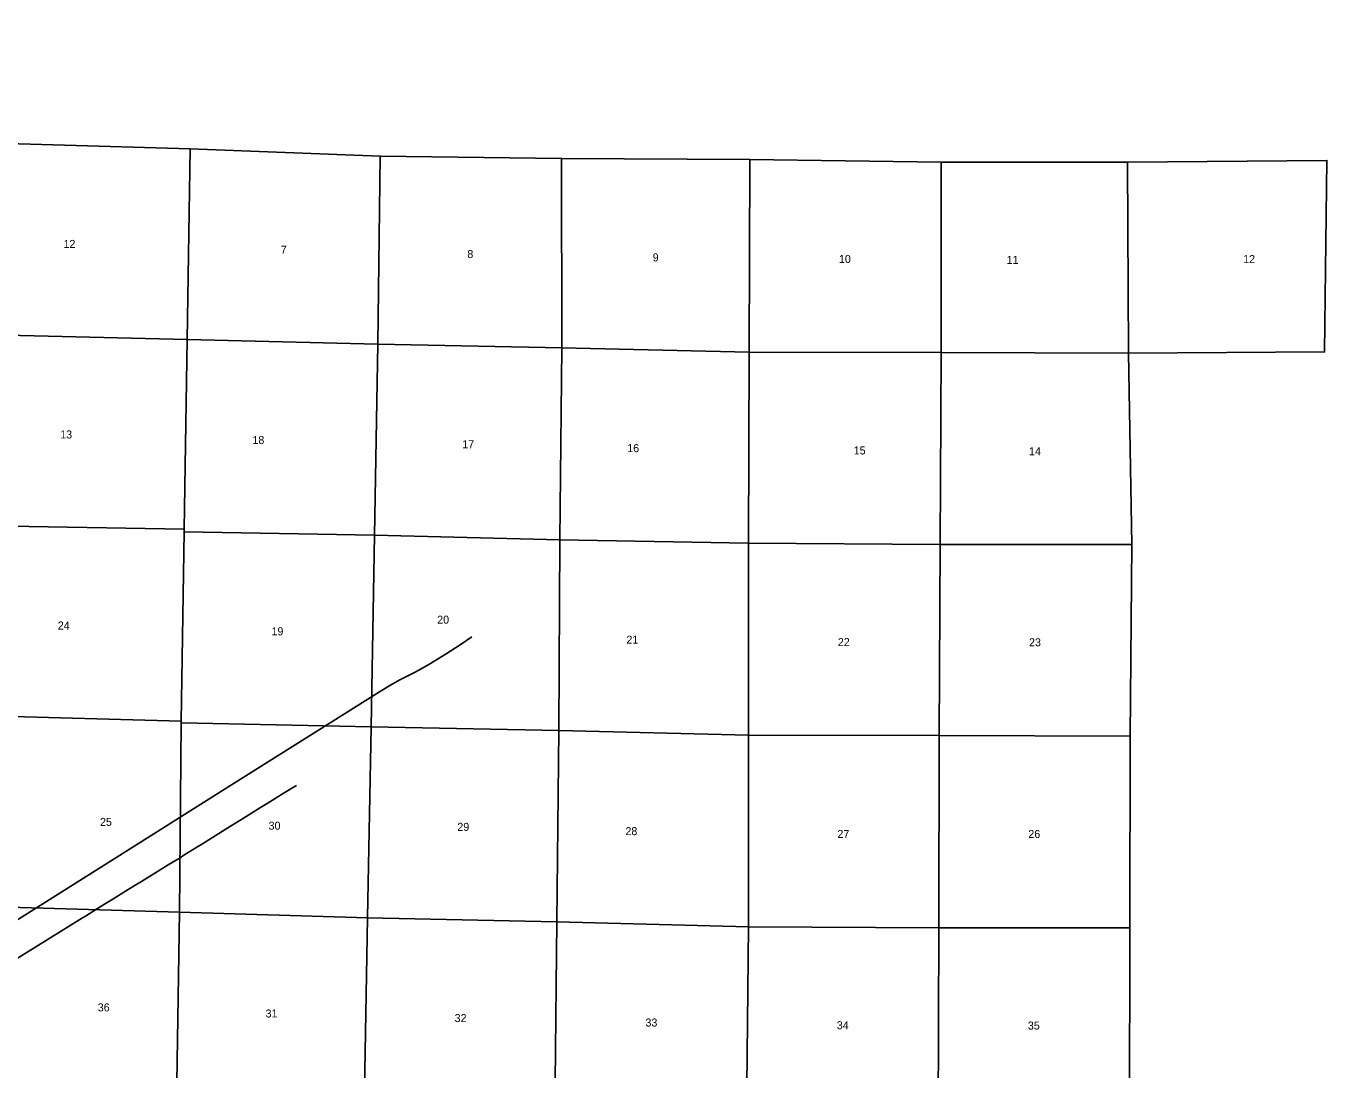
# Model space of a CAD drawing. Extents: x 1587405 to 1714697, y 1028970 to 1155083.
# Drawn here: x 1678758 to 1714697, y 1124403 to 1153249 of the extents above; entities that cross this region are included whole.
import ezdxf

# ---------------------------------------------------------------- set-up
doc = ezdxf.new("R2010")
doc.units = 0
for name, color, linetype in [('GM_X_Rail_Line', 7, 'Continuous'), ('GM_X_Section', 7, 'Continuous'), ('GM_X_Section_Text', 7, 'Continuous'), ('GM_X_State_Location', 7, 'Continuous'), ('GM_X_State_Route', 7, 'Continuous')]:
    doc.layers.add(name, color=color, linetype=linetype)

msp = doc.modelspace()

# ---------------------------------------------------------------- linework, layer by layer
at = {"layer": 'GM_X_Rail_Line'}
msp.add_lwpolyline([(1653568, 1112819), (1655300, 1113913), (1659870, 1116798), (1669731, 1123017), (1672359, 1124671), (1681695, 1130554), (1684437, 1132280), (1688527, 1134851), (1688807, 1135025), (1688953, 1135113), (1689087, 1135186), (1689268, 1135279), (1689470, 1135381), (1689588, 1135442), (1689734, 1135522), (1689884, 1135608), (1690363, 1135905), (1690749, 1136148), (1691070, 1136368)], dxfattribs=at)
at = {"layer": 'GM_X_Section'}
for points in [[(1677925, 1150009), (1683291, 1149852), (1683213, 1144589), (1677820, 1144716)], [(1683291, 1149852), (1688546, 1149656), (1688481, 1144459), (1683213, 1144589)], [(1688546, 1149656), (1693552, 1149588), (1693560, 1144355), (1688481, 1144459)], [(1693552, 1149588), (1698753, 1149557), (1698738, 1144239), (1693560, 1144355)], [(1698753, 1149557), (1704038, 1149488), (1704038, 1144224), (1698738, 1144239)], [(1704038, 1149488), (1709184, 1149491), (1709215, 1144207), (1704038, 1144224)], [(1709184, 1149491), (1714697, 1149534), (1714631, 1144244), (1709215, 1144207)], [(1683213, 1144589), (1683123, 1139347), (1677747, 1139442), (1677820, 1144716)], [(1688481, 1144459), (1688381, 1139180), (1683127, 1139277), (1683123, 1139347), (1683213, 1144589)], [(1693560, 1144355), (1693509, 1139051), (1688381, 1139180), (1688481, 1144459)], [(1698738, 1144239), (1698718, 1138958), (1693509, 1139051), (1693560, 1144355)], [(1704038, 1144224), (1704015, 1138925), (1698718, 1138958), (1698738, 1144239)], [(1709215, 1144207), (1709305, 1138921), (1704015, 1138925), (1704038, 1144224)], [(1677747, 1139442), (1683123, 1139347), (1683127, 1139277), (1683047, 1134044), (1677705, 1134187)], [(1683127, 1139277), (1688381, 1139180), (1688295, 1133887), (1683047, 1133992), (1683047, 1134044)], [(1688381, 1139180), (1693509, 1139051), (1693475, 1133782), (1688295, 1133887)], [(1693509, 1139051), (1698718, 1138958), (1698713, 1133652), (1693475, 1133782)], [(1698718, 1138958), (1704015, 1138925), (1703979, 1133642), (1698713, 1133652)], [(1704015, 1138925), (1709305, 1138921), (1709258, 1133625), (1703979, 1133642)], [(1677705, 1134187), (1683047, 1134044), (1683047, 1133992), (1682995, 1128763), (1677648, 1128918)], [(1683047, 1133992), (1688295, 1133887), (1688193, 1128606), (1682995, 1128763)], [(1688295, 1133887), (1693475, 1133782), (1693423, 1128497), (1688193, 1128606)], [(1698713, 1133652), (1698713, 1128358), (1693423, 1128497), (1693475, 1133782)], [(1703979, 1133642), (1703978, 1128334), (1698713, 1128358), (1698713, 1133652)], [(1709258, 1133625), (1709254, 1128334), (1703978, 1128334), (1703979, 1133642)], [(1677648, 1128918), (1682995, 1128763), (1682911, 1123475), (1677670, 1123620)], [(1682995, 1128763), (1688193, 1128606), (1688097, 1123318), (1682911, 1123475)], [(1688193, 1128606), (1693423, 1128497), (1693370, 1123188), (1688675, 1123293), (1688097, 1123318)], [(1693423, 1128497), (1698713, 1128358), (1698662, 1123069), (1693792, 1123177), (1693370, 1123188)], [(1698713, 1128358), (1703978, 1128334), (1703954, 1123061), (1698938, 1123070), (1698662, 1123069)], [(1703978, 1128334), (1709254, 1128334), (1709239, 1123064), (1704090, 1123055), (1703954, 1123061)]]:
    msp.add_lwpolyline(points, close=True, dxfattribs=at)
at = {"layer": 'GM_X_State_Route'}
msp.add_lwpolyline([(1678346, 1127383), (1679713, 1128231), (1679978, 1128396), (1680316, 1128604), (1680397, 1128654), (1680731, 1128862), (1680997, 1129028), (1681108, 1129096), (1681584, 1129389), (1681794, 1129518), (1681947, 1129613), (1682687, 1130070), (1683014, 1130269), (1683118, 1130335), (1683480, 1130560), (1683633, 1130656), (1683982, 1130872), (1684287, 1131065), (1684692, 1131315), (1684985, 1131496), (1685236, 1131652), (1685418, 1131764), (1685893, 1132057), (1686214, 1132255), (1686231, 1132265)], dxfattribs=at)

# ---------------------------------------------------------------- texts
at = {"layer": 'GM_X_Section_Text'}
for s, p in [('12', (1679794, 1147117)), ('7', (1685796, 1146955)), ('8', (1690950, 1146838)), ('9', (1696070, 1146746)), ('10', (1701216, 1146702)), ('11', (1705847, 1146677)), ('12', (1712381, 1146699)), ('13', (1679702, 1141853)), ('18', (1685013, 1141699)), ('17', (1690810, 1141583)), ('16', (1695366, 1141474)), ('15', (1701623, 1141411)), ('14', (1706465, 1141388)), ('24', (1679636, 1136574)), ('20', (1690117, 1136736)), ('19', (1685539, 1136414)), ('21', (1695344, 1136183)), ('22', (1701185, 1136117)), ('23', (1706467, 1136111)), ('25', (1680802, 1131148)), ('30', (1685459, 1131044)), ('29', (1690673, 1131011)), ('28', (1695317, 1130892)), ('27', (1701174, 1130813)), ('26', (1706447, 1130813)), ('36', (1680740, 1126022)), ('31', (1685376, 1125854)), ('32', (1690598, 1125727)), ('33', (1695870, 1125604)), ('34', (1701156, 1125529)), ('35', (1706434, 1125520))]:
    msp.add_text(s, height=221, rotation=0, dxfattribs=at).set_placement(p)
at = {"layer": 'GM_X_State_Location'}
for s, p in [('18', (1707633, 1153175)), ('18', (1681515, 1150333)), ('12', (1707809, 1146166)), ('12', (1687393, 1132715))]:
    msp.add_text(s, height=1, rotation=0, dxfattribs=at).set_placement(p)
for s, p in [('s', (1707885, 1153248)), ('r', (1707885, 1153248)), ('s', (1681767, 1150405)), ('r', (1681767, 1150405)), ('s', (1708061, 1146239)), ('r', (1708061, 1146239)), ('s', (1687645, 1132788)), ('r', (1687645, 1132788))]:
    msp.add_text(s, height=1, dxfattribs=at).set_placement(p)

doc.saveas('drawing.dxf')
